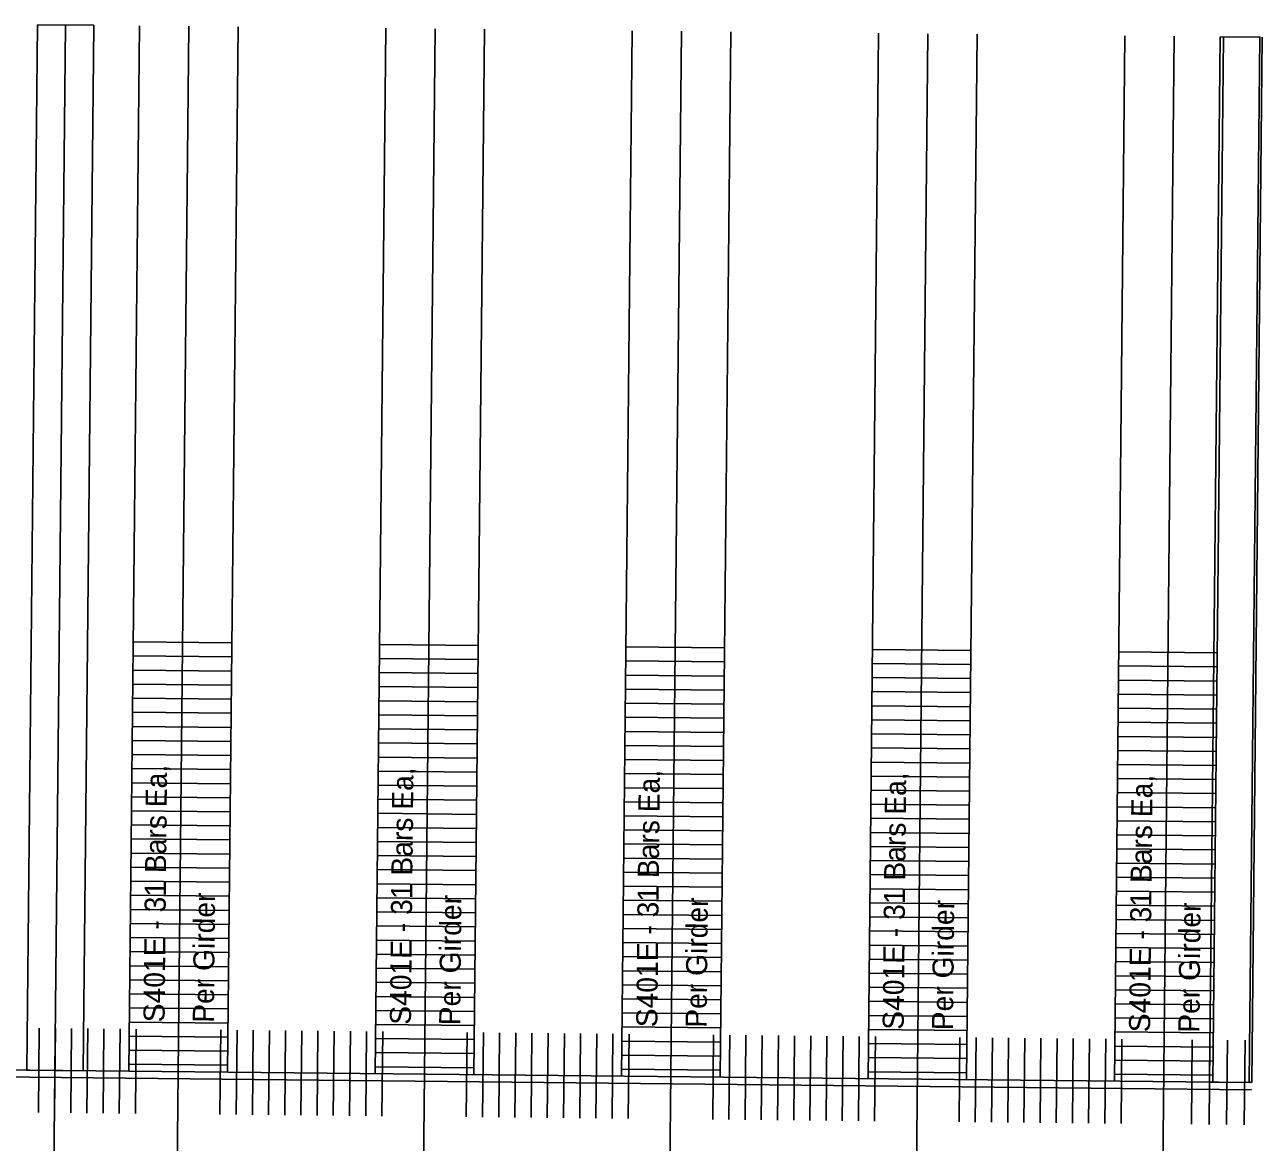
# Model space of a CAD drawing. Extents: x 632547 to 633311, y 380830 to 386139.
# Drawn here: x 633168.86 to 633212.8, y 380897.55 to 380937.24 of the extents above; entities that cross this region are included whole.
import ezdxf

# ---------------------------------------------------------------- set-up
doc = ezdxf.new("R2010")
doc.units = 0
for name, color, linetype in [('B_Border', 7, 'Continuous'), ('B_Boring Annot', 7, 'Continuous'), ('R_Border_Scale', 7, 'Continuous'), ('R_Wall', 7, 'Continuous')]:
    doc.layers.add(name, color=color, linetype=linetype)

msp = doc.modelspace()

# ---------------------------------------------------------------- linework, layer by layer
at = {"layer": 'B_Border'}
for p, q in [((633174.68, 380937.182), (633174.247, 380894.425)), ((633183.429, 380937.094), (633182.997, 380894.336)), ((633192.179, 380937.005), (633191.746, 380894.248)), ((633200.928, 380936.917), (633200.496, 380894.159)), ((633209.678, 380936.828), (633209.245, 380894.071)), ((633212.425, 380899.415), (633095.371, 380900.599))]:
    msp.add_line(p, q, dxfattribs=at)
at = {"layer": 'B_Boring Annot'}
for p, q in [((633168.929, 380900.105), (633169.305, 380937.237)), ((633170.929, 380900.085), (633171.305, 380937.217)), ((633172.93, 380937.2), (633172.554, 380900.069)), ((633176.43, 380937.165), (633176.054, 380900.033)), ((633181.679, 380937.112), (633181.304, 380899.98)), ((633185.179, 380937.076), (633184.803, 380899.945)), ((633190.429, 380937.023), (633190.053, 380899.891)), ((633193.929, 380936.988), (633193.553, 380899.856)), ((633199.178, 380936.935), (633198.803, 380899.803)), ((633202.678, 380936.899), (633202.303, 380899.768)), ((633207.928, 380936.846), (633207.552, 380899.714)), ((633210.927, 380899.68), (633211.303, 380936.812)), ((633211.428, 380936.811), (633211.052, 380899.679)), ((633212.344, 380899.666), (633212.719, 380936.798)), ((633212.427, 380899.665), (633212.803, 380936.797)), ((633127.431, 380900.525), (633212.427, 380899.665))]:
    msp.add_line(p, q, dxfattribs=at)
for points in [[(633169.305, 380937.237), (633171.305, 380937.217), (633170.929, 380900.085), (633168.929, 380900.105)], [(633211.303, 380936.812), (633212.719, 380936.798), (633212.344, 380899.666), (633210.927, 380899.68)]]:
    msp.add_lwpolyline(points, close=True, dxfattribs=at)
at = {"layer": 'R_Border_Scale'}
for p, q in [((633176.208, 380915.282), (633172.708, 380915.318)), ((633184.958, 380915.194), (633181.458, 380915.229)), ((633176.203, 380914.782), (633172.703, 380914.818)), ((633193.707, 380915.105), (633190.207, 380915.141)), ((633202.457, 380915.017), (633198.957, 380915.052)), ((633211.206, 380914.928), (633207.707, 380914.964)), ((633176.198, 380914.282), (633172.698, 380914.318)), ((633184.953, 380914.694), (633181.453, 380914.729)), ((633193.702, 380914.605), (633190.202, 380914.641)), ((633202.452, 380914.517), (633198.952, 380914.552)), ((633211.201, 380914.428), (633207.702, 380914.464)), ((633184.948, 380914.194), (633181.448, 380914.229)), ((633193.697, 380914.105), (633190.197, 380914.141)), ((633202.447, 380914.017), (633198.947, 380914.052)), ((633211.196, 380913.928), (633207.696, 380913.964)), ((633176.193, 380913.782), (633172.693, 380913.818)), ((633184.943, 380913.694), (633181.443, 380913.729)), ((633193.692, 380913.605), (633190.192, 380913.641)), ((633202.442, 380913.517), (633198.942, 380913.552)), ((633211.191, 380913.428), (633207.691, 380913.464)), ((633176.188, 380913.282), (633172.688, 380913.318)), ((633184.938, 380913.194), (633181.438, 380913.229)), ((633193.687, 380913.105), (633190.187, 380913.141)), ((633202.437, 380913.017), (633198.937, 380913.052)), ((633176.183, 380912.782), (633172.683, 380912.818)), ((633184.932, 380912.694), (633181.433, 380912.729)), ((633193.682, 380912.605), (633190.182, 380912.641)), ((633202.432, 380912.517), (633198.932, 380912.552)), ((633211.186, 380912.928), (633207.686, 380912.964)), ((633176.178, 380912.282), (633172.678, 380912.318)), ((633184.927, 380912.194), (633181.428, 380912.229)), ((633193.677, 380912.105), (633190.177, 380912.141)), ((633211.181, 380912.428), (633207.681, 380912.464)), ((633176.173, 380911.783), (633172.673, 380911.818)), ((633184.922, 380911.694), (633181.423, 380911.729)), ((633202.427, 380912.017), (633198.927, 380912.052)), ((633211.176, 380911.928), (633207.676, 380911.964)), ((633176.168, 380911.283), (633172.668, 380911.318)), ((633184.917, 380911.194), (633181.417, 380911.229)), ((633193.672, 380911.605), (633190.172, 380911.641)), ((633202.421, 380911.517), (633198.922, 380911.552)), ((633211.171, 380911.428), (633207.671, 380911.464)), ((633176.163, 380910.783), (633172.663, 380910.818)), ((633193.667, 380911.106), (633190.167, 380911.141)), ((633202.416, 380911.017), (633198.917, 380911.052)), ((633211.166, 380910.928), (633207.666, 380910.964)), ((633184.912, 380910.694), (633181.412, 380910.729)), ((633193.662, 380910.606), (633190.162, 380910.641)), ((633202.411, 380910.517), (633198.912, 380910.552)), ((633211.161, 380910.428), (633207.661, 380910.464)), ((633176.158, 380910.283), (633172.658, 380910.318)), ((633184.907, 380910.194), (633181.407, 380910.229)), ((633193.657, 380910.106), (633190.157, 380910.141)), ((633202.406, 380910.017), (633198.906, 380910.052)), ((633211.156, 380909.929), (633207.656, 380909.964)), ((633176.153, 380909.783), (633172.653, 380909.818)), ((633184.902, 380909.694), (633181.402, 380909.73)), ((633193.652, 380909.606), (633190.152, 380909.641)), ((633202.401, 380909.517), (633198.901, 380909.552)), ((633176.148, 380909.283), (633172.648, 380909.318)), ((633184.897, 380909.194), (633181.397, 380909.23)), ((633193.647, 380909.106), (633190.147, 380909.141)), ((633202.396, 380909.017), (633198.896, 380909.052)), ((633211.151, 380909.429), (633207.651, 380909.464)), ((633176.142, 380908.783), (633172.643, 380908.818)), ((633184.892, 380908.694), (633181.392, 380908.73)), ((633193.642, 380908.606), (633190.142, 380908.641)), ((633211.146, 380908.929), (633207.646, 380908.964)), ((633176.137, 380908.283), (633172.638, 380908.318)), ((633184.887, 380908.194), (633181.387, 380908.23)), ((633202.391, 380908.517), (633198.891, 380908.553)), ((633211.141, 380908.429), (633207.641, 380908.464)), ((633176.132, 380907.783), (633172.633, 380907.818)), ((633184.882, 380907.694), (633181.382, 380907.73)), ((633193.637, 380908.106), (633190.137, 380908.141)), ((633202.386, 380908.017), (633198.886, 380908.053)), ((633211.136, 380907.929), (633207.636, 380907.964)), ((633176.127, 380907.283), (633172.627, 380907.318)), ((633193.631, 380907.606), (633190.132, 380907.641)), ((633202.381, 380907.517), (633198.881, 380907.553)), ((633211.131, 380907.429), (633207.631, 380907.464)), ((633184.877, 380907.194), (633181.377, 380907.23)), ((633193.626, 380907.106), (633190.127, 380907.141)), ((633202.376, 380907.017), (633198.876, 380907.053)), ((633211.125, 380906.929), (633207.626, 380906.964)), ((633176.122, 380906.783), (633172.622, 380906.818)), ((633184.872, 380906.694), (633181.372, 380906.73)), ((633193.621, 380906.606), (633190.122, 380906.641)), ((633202.371, 380906.517), (633198.871, 380906.553)), ((633211.12, 380906.429), (633207.621, 380906.464)), ((633176.117, 380906.283), (633172.617, 380906.318)), ((633184.867, 380906.194), (633181.367, 380906.23)), ((633193.616, 380906.106), (633190.116, 380906.141)), ((633202.366, 380906.017), (633198.866, 380906.053)), ((633211.115, 380905.929), (633207.616, 380905.964)), ((633176.112, 380905.783), (633172.612, 380905.818)), ((633184.862, 380905.694), (633181.362, 380905.73)), ((633193.611, 380905.606), (633190.111, 380905.641)), ((633202.361, 380905.517), (633198.861, 380905.553)), ((633176.107, 380905.283), (633172.607, 380905.318)), ((633184.857, 380905.194), (633181.357, 380905.23)), ((633193.606, 380905.106), (633190.106, 380905.141)), ((633211.11, 380905.429), (633207.61, 380905.464)), ((633176.102, 380904.783), (633172.602, 380904.818)), ((633184.852, 380904.694), (633181.352, 380904.73)), ((633193.601, 380904.606), (633190.101, 380904.641)), ((633202.356, 380905.017), (633198.856, 380905.053)), ((633211.105, 380904.929), (633207.605, 380904.964)), ((633176.097, 380904.283), (633172.597, 380904.318)), ((633184.846, 380904.194), (633181.347, 380904.23)), ((633202.351, 380904.517), (633198.851, 380904.553)), ((633211.1, 380904.429), (633207.6, 380904.464)), ((633176.092, 380903.783), (633172.592, 380903.818)), ((633193.596, 380904.106), (633190.096, 380904.141)), ((633202.346, 380904.017), (633198.846, 380904.053)), ((633211.095, 380903.929), (633207.595, 380903.964)), ((633176.087, 380903.283), (633172.587, 380903.318)), ((633184.841, 380903.694), (633181.342, 380903.73)), ((633193.591, 380903.606), (633190.091, 380903.641)), ((633202.341, 380903.517), (633198.841, 380903.553)), ((633211.09, 380903.429), (633207.59, 380903.464)), ((633184.836, 380903.194), (633181.337, 380903.23)), ((633193.586, 380903.106), (633190.086, 380903.141)), ((633202.335, 380903.017), (633198.836, 380903.053)), ((633211.085, 380902.929), (633207.585, 380902.964)), ((633176.082, 380902.783), (633172.582, 380902.818)), ((633184.831, 380902.694), (633181.331, 380902.73)), ((633193.581, 380902.606), (633190.081, 380902.641)), ((633202.33, 380902.517), (633198.831, 380902.553)), ((633211.08, 380902.429), (633207.58, 380902.464)), ((633176.077, 380902.283), (633172.577, 380902.318)), ((633184.826, 380902.194), (633181.326, 380902.23)), ((633193.576, 380902.106), (633190.076, 380902.141)), ((633202.325, 380902.017), (633198.826, 380902.053)), ((633169.369, 380901.601), (633169.339, 380898.601)), ((633169.944, 380901.595), (633169.914, 380898.595)), ((633170.519, 380901.589), (633170.489, 380898.589)), ((633171.094, 380901.583), (633171.064, 380898.584)), ((633171.669, 380901.578), (633171.639, 380898.578)), ((633172.244, 380901.572), (633172.214, 380898.572)), ((633176.072, 380901.783), (633172.572, 380901.818)), ((633172.819, 380901.566), (633172.789, 380898.566)), ((633184.821, 380901.695), (633181.321, 380901.73)), ((633193.571, 380901.606), (633190.071, 380901.641)), ((633211.075, 380901.929), (633207.575, 380901.964)), ((633176.067, 380901.283), (633172.567, 380901.318)), ((633175.819, 380901.536), (633175.789, 380898.536)), ((633176.394, 380901.53), (633176.364, 380898.53)), ((633176.969, 380901.524), (633176.939, 380898.524)), ((633177.544, 380901.518), (633177.514, 380898.518)), ((633178.119, 380901.512), (633178.089, 380898.512)), ((633178.694, 380901.506), (633178.664, 380898.507)), ((633179.269, 380901.501), (633179.239, 380898.501)), ((633179.844, 380901.495), (633179.814, 380898.495)), ((633180.419, 380901.489), (633180.389, 380898.489)), ((633180.994, 380901.483), (633180.964, 380898.483)), ((633184.816, 380901.195), (633181.316, 380901.23)), ((633181.569, 380901.477), (633181.538, 380898.478)), ((633184.569, 380901.447), (633184.538, 380898.447)), ((633185.144, 380901.441), (633185.113, 380898.441)), ((633185.719, 380901.435), (633185.688, 380898.436)), ((633186.294, 380901.43), (633186.263, 380898.43)), ((633186.869, 380901.424), (633186.838, 380898.424)), ((633187.444, 380901.418), (633187.413, 380898.418)), ((633188.019, 380901.412), (633187.988, 380898.412)), ((633188.593, 380901.406), (633188.563, 380898.406)), ((633189.168, 380901.401), (633189.138, 380898.401)), ((633189.743, 380901.395), (633189.713, 380898.395)), ((633193.566, 380901.106), (633190.066, 380901.141)), ((633190.318, 380901.389), (633190.288, 380898.389)), ((633193.318, 380901.359), (633193.288, 380898.359)), ((633193.893, 380901.353), (633193.863, 380898.353)), ((633194.468, 380901.347), (633194.438, 380898.347)), ((633195.043, 380901.341), (633195.013, 380898.341)), ((633195.618, 380901.335), (633195.588, 380898.335)), ((633196.193, 380901.329), (633196.163, 380898.33)), ((633196.768, 380901.324), (633196.738, 380898.324)), ((633197.343, 380901.318), (633197.313, 380898.318)), ((633197.918, 380901.312), (633197.888, 380898.312)), ((633198.493, 380901.306), (633198.463, 380898.306)), ((633202.32, 380901.517), (633198.82, 380901.553)), ((633199.068, 380901.3), (633199.038, 380898.301)), ((633202.068, 380901.27), (633202.037, 380898.27)), ((633202.643, 380901.264), (633202.612, 380898.264)), ((633203.218, 380901.258), (633203.187, 380898.259)), ((633203.793, 380901.253), (633203.762, 380898.253)), ((633204.368, 380901.247), (633204.337, 380898.247)), ((633204.943, 380901.241), (633204.912, 380898.241)), ((633205.518, 380901.235), (633205.487, 380898.235)), ((633206.093, 380901.229), (633206.062, 380898.229)), ((633206.668, 380901.223), (633206.637, 380898.224)), ((633207.243, 380901.218), (633207.212, 380898.218)), ((633211.07, 380901.429), (633207.57, 380901.464)), ((633207.817, 380901.212), (633207.787, 380898.212)), ((633210.317, 380901.187), (633210.287, 380898.187)), ((633210.942, 380901.18), (633210.912, 380898.18)), ((633211.567, 380901.174), (633211.537, 380898.174)), ((633212.192, 380901.168), (633212.162, 380898.168)), ((633176.062, 380900.783), (633172.562, 380900.818)), ((633184.811, 380900.695), (633181.311, 380900.73)), ((633202.315, 380901.017), (633198.815, 380901.053)), ((633211.065, 380900.929), (633207.565, 380900.964)), ((633176.056, 380900.283), (633172.557, 380900.319)), ((633193.561, 380900.606), (633190.061, 380900.641)), ((633202.31, 380900.518), (633198.81, 380900.553)), ((633211.06, 380900.429), (633207.56, 380900.464)), ((633184.806, 380900.195), (633181.306, 380900.23)), ((633193.556, 380900.106), (633190.056, 380900.141)), ((633202.305, 380900.018), (633198.805, 380900.053)), ((633211.055, 380899.929), (633207.555, 380899.964))]:
    msp.add_line(p, q, dxfattribs=at)
at = {"layer": 'R_Wall'}
msp.add_line((633170.305, 380937.227), (633169.872, 380894.469), dxfattribs=at)

# ---------------------------------------------------------------- texts
for s, p in [('S401E - 31 Bars Ea,', (633173.822, 380901.806)), ('S401E - 31 Bars Ea,', (633182.571, 380901.717)), ('S401E - 31 Bars Ea,', (633191.321, 380901.629)), ('S401E - 31 Bars Ea,', (633200.07, 380901.54)), ('S401E - 31 Bars Ea,', (633208.82, 380901.452)), ('Per Girder', (633175.572, 380901.788)), ('Per Girder', (633184.321, 380901.7)), ('Per Girder', (633193.071, 380901.611)), ('Per Girder', (633201.82, 380901.523)), ('Per Girder', (633210.57, 380901.434))]:
    msp.add_text(s, height=0.75, rotation=89.4304, dxfattribs=at).set_placement(p)

doc.saveas('drawing.dxf')
